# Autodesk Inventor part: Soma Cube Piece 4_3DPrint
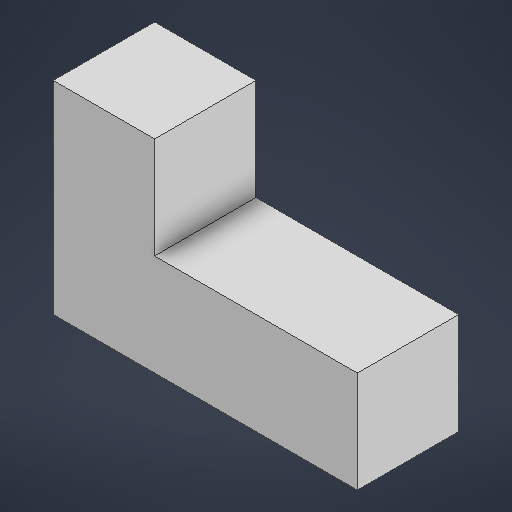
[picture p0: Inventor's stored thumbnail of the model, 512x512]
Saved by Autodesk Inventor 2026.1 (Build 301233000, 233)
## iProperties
Created: 2025-12
Part Number: Soma Cube Piece 4_3DPrint
Material: Generic
Document SubType Name: Modeling
Designer: egberbos000
Density: 1 g/cm^3
Appearance: Default
Author: egberbos000
Part Number: Soma Cube Piece 4
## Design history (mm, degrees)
sketch "Sketch1"
  geometry: L1 (0, 0)-(50.8, 0); L2 (50.8, 0)-(50.8, 25.4); L3 (50.8, 25.4)-(0, 25.4); L4 (0, 25.4)-(0, 0); L5 (50.8, 25.4)-(76.2, 25.4); L6 (76.2, 25.4)-(76.2, 0); L7 (76.2, 0)-(50.8, 0); L8 (50.8, 0)-(50.8, 25.4); L9 (25.4, 25.4)-(0, 25.4); L10 (0, 25.4)-(0, 50.8); L11 (0, 50.8)-(25.4, 50.8); L12 (25.4, 50.8)-(25.4, 25.4); 2 further points
  constraints: 24 end point, 6 parallel, 3 horizontal, 3 perpendicular, 1 midpoint
  dimensions: "d0" = 50.8 distance of L2.end L3.end; "d1" = 25.4 distance of L1.end L2.end; "d2" = 25.4 distance of L5.end L6.end (= d1); "d3" = 25.4 distance of L6.end L7.end (= d1); "d4" = 25.4 distance of L10.end L11.end; "d5" = 25.4 distance of L11.end L9.start
extrude "Extrusion1" new body sketch "Sketch1" distance "d6" = 25.4 (= d2); taper "d7" = 0 deg
body "Solid1"
